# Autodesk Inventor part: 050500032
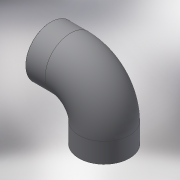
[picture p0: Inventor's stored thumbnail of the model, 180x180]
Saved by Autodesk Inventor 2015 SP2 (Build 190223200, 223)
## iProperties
Created: 2017-10
Part Number: 050500032
Material: Generic
Description: PLASSON 90° ELBOW-CEMENT PVC 32
Document SubType Name: Modeling
Designer: KIM
Density: 1 g/cm^3
Appearance: Default
Author: KIM
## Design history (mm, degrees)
derived "050500.ipt"
feature "Solid1::050500.ipt"
tag "TaggingFeature1"
body "Solid1"
other parameters: "d1" = 39, "d4" = 32, "d5" = 28.8, "d7" = 0.32, "d9" = 39, "d10" = 38.5, "d13" = 90 deg, "d18" = 17, "d19" = 90 deg, "d20" = 32, "d21" = 22, "d22" = 0, "d24" = 90 deg, "d26" = 28.8, "d27" = 90 deg, "d_" = 32, "E_" = 39, "H_" = 58, "l_" = 22, "Z_" = 17
